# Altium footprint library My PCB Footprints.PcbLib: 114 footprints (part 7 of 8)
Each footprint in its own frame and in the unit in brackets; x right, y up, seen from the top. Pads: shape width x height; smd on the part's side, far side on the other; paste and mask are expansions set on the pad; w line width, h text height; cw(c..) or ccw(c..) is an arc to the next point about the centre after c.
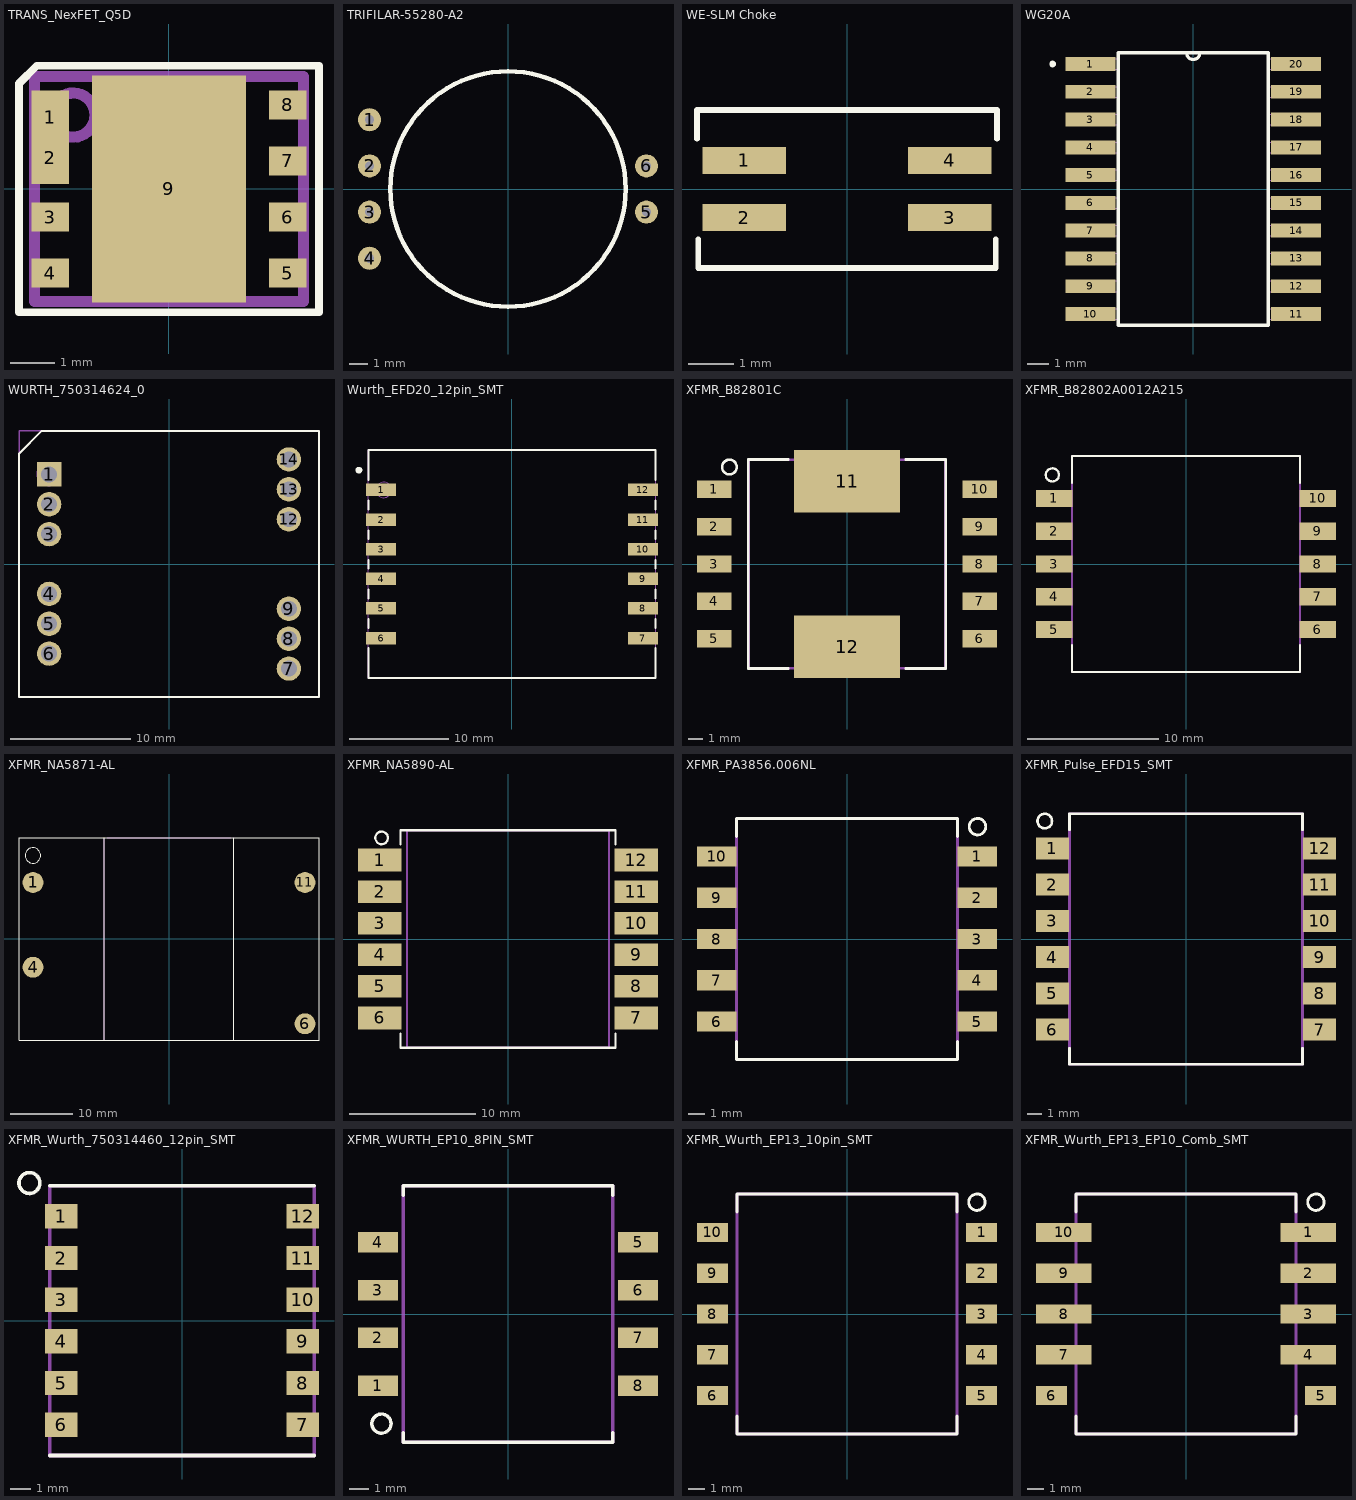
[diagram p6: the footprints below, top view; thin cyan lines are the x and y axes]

## TRANS_NexFET_Q5D [mm] "TI recommended land pattern (nominal) M0188-01"
height 1.5
pads (9):
  rect 0.85x1.2 smd paste-0.1 mask+0.051: 1(-2.695,1.63) 2(-2.695,0.71)
  rect 0.85x0.65 smd paste-0.1 mask+0.051: 3(-2.695,-0.635) 4(-2.695,-1.905) 5(2.695,-1.905) 6(2.695,-0.635) 7(2.695,0.635) 8(2.695,1.905)
  rect 3.48x5.15 smd paste-2.2 mask+0.051: 9(0,0)
Top Overlay:
  lines w0.178: -3.4,-2.795 -3.4,0 -3.4,2.39 -2.995,2.795 0,2.795 3.4,2.795 3.4,0 3.4,-2.795 0,-2.795 -3.4,-2.795
Top Paste:
  region: 0.15,0.15 0.15,2.125 1.45,2.125 1.45,0.15
  region: -1.45,0.15 -1.45,2.125 -0.15,2.125 -0.15,0.15
  region: 0.15,-2.125 0.15,-0.15 1.45,-0.15 1.45,-2.125
  region: -1.45,-2.125 -1.45,-0.15 -0.15,-0.15 -0.15,-2.125
Mechanical 5:
  text ".Designator" at -1.529,-0.508 h1.02
Mechanical 13:
  circle w0.254: c-2.175,1.675 r0.5
  lines w0.254: -3.05,-2.55 3.05,-2.55 3.05,2.55 -3.05,2.55 -3.05,-2.55
3D body: height 1.51, standoff 1, extent -2.684,1.166 -1.666,2.184
3D body: height 1.5, standoff 0, extent -3.05,-2.549 3.049,2.549

## TRIFILAR-55280-A2 [mil]
height 250
pads (6):
  round 50 hole 20: 1(-300,150) 2(-300,50) 3(-300,-50) 4(-300,-150) 5(300,-50) 6(300,50)
Top Overlay:
  circle w10: c0,0 r255

## WE-SLM Choke [mm] "WE-SLM SMD Common Mode Choke"
height 3.3
pads (4):
  rect 1.85x0.6 smd: 1(-2.275,0.635) 2(-2.275,-0.635) 3(2.275,-0.635) 4(2.275,0.635)
Top Overlay:
  lines w0.127: -3.327,1.118 -3.327,1.753 ; -3.302,-1.753 -3.302,-1.118 ; -3.302,-1.75 3.302,-1.75 ; -3.302,1.75 3.302,1.75 ; 3.302,-1.753 3.302,-1.118 ; 3.327,1.118 3.327,1.753
  text "." at -3.937,0.635 h1
  text "." at -3.937,-0.762 h1
Mechanical 5:
  text ".Designator" at -0.127,0 h1.02
3D body: height 3.3, standoff 0, extent -3.023,-1.651 3.023,1.651

## WG20A [mil]
pads (20):
  rect 90x25 smd: 1(-185,225) 2(-185,175) 3(-185,125) 4(-185,75) 5(-185,25) 6(-185,-25) 7(-185,-75) 8(-185,-125) 9(-185,-175) 10(-185,-225) 11(185,-225) 12(185,-175) 13(185,-125) 14(185,-75) 15(185,-25) 16(185,25) 17(185,75) 18(185,125) 19(185,175) 20(185,225)
Top Overlay:
  circle w6: c-253,225 r3
  lines w6: -12,245 ccw(c0,245) 12,245 ; -135,-245 135,-245 135,245 -135,245 -135,-245
Mechanical 1:
  circle w1: c-253,225 r3
  lines w1: -12,245 ccw(c0,245) 12,245 ; -210,-234.5 -135,-234.5 -135,-215.5 -210,-215.5 -210,-234.5 ; -210,-184.5 -135,-184.5 -135,-165.5 -210,-165.5 -210,-184.5 ; -210,-134.5 -210,-115.5 -135,-115.5 -135,-134.5 -210,-134.5 ; -210,-84.5 -210,-65.5 -135,-65.5 -135,-84.5 -210,-84.5 ; -210,-34.5 -210,-15.5 -135,-15.5 -135,-34.5 -210,-34.5 ; -210,15.5 -210,34.5 -135,34.5 -135,15.5 -210,15.5 ; -210,65.5 -210,84.5 -135,84.5 -135,65.5 -210,65.5 ; -210,115.5 -210,134.5 -135,134.5 -135,115.5 -210,115.5 ; -210,165.5 -210,184.5 -135,184.5 -135,165.5 -210,165.5 ; -210,215.5 -210,234.5 -135,234.5 -135,215.5 -210,215.5 ; -135,-245 135,-245 135,245 -135,245 -135,-245 ; 135,-234.5 210,-234.5 210,-215.5 135,-215.5 135,-234.5 ; 135,-184.5 210,-184.5 210,-165.5 135,-165.5 135,-184.5 ; 135,-134.5 135,-115.5 210,-115.5 210,-134.5 135,-134.5 ; 135,-84.5 135,-65.5 210,-65.5 210,-84.5 135,-84.5 ; 135,-34.5 135,-15.5 210,-15.5 210,-34.5 135,-34.5 ; 135,15.5 135,34.5 210,34.5 210,15.5 135,15.5 ; 135,65.5 135,84.5 210,84.5 210,65.5 135,65.5 ; 135,115.5 135,134.5 210,134.5 210,115.5 135,115.5 ; 135,165.5 135,184.5 210,184.5 210,165.5 135,165.5 ; 135,215.5 135,234.5 210,234.5 210,215.5 135,215.5

## WURTH_750314624_0 [mil] "WURTH EF20 through-hole, extended rail"
height 629.92
pads (12):
  rect 80x80 hole 52: 1(-393.5,294)
  round 80 hole 52: 2(-393.5,196) 3(-393.5,98) 4(-393.5,-98) 5(-393.5,-196) 6(-393.5,-294) 7(393.5,-343) 8(393.5,-245) 9(393.5,-147) 12(393.5,147) 13(393.5,245) 14(393.5,343)
Top Overlay:
  lines w6.69: -492.13,-437.01 -492.13,362.2 -417.32,437.01 492.13,437.01 492.13,-437.01 -492.13,-437.01
Mechanical 5:
  circle w40: c-395,295 r20
  lines w5: -492,-437 492,-437 492,437 -492,437 -492,-437
  text ".Designator" at -75,-15 h40
3D body: height 630, standoff 150, extent -335,-275 275,270
3D body: height 500, standoff 100, extent -50,-435 490,435
3D body: height 100, standoff 0, extent 338.7,-437.49 460,435
3D body: height 500, standoff 100, extent -490,-435 -50,435
3D body: height 501, standoff 400, extent -415.37,274.63 -374.63,315.37
3D body: height 100, standoff 0, extent -455,-435 -333.7,437.49

## Wurth_EFD20_12pin_SMT [mm] "WURTH EFD20 12pin SMT package"
height 11.43
pads (12):
  rect 3.05x1.27 smd: 1(-13.26,7.5) 2(-13.26,4.5) 3(-13.26,1.5) 4(-13.26,-1.5) 5(-13.26,-4.5) 6(-13.26,-7.5) 7(13.26,-7.5) 8(13.26,-4.5) 9(13.26,-1.5) 10(13.26,1.5) 11(13.26,4.5) 12(13.26,7.5)
Top Overlay:
  circle w0.5: c-15.5,9.5 r0.091
  lines w0.2: -14.54,-8.509 -14.54,-11.555 14.54,-11.555 14.54,-8.509 ; -14.54,-6.477 -14.54,-5.588 ; -14.54,-3.477 -14.54,-2.588 ; -14.54,-0.477 -14.54,0.412 ; -14.54,2.523 -14.54,3.412 ; -14.54,5.523 -14.54,6.412 ; -14.54,8.509 -14.54,11.555 14.54,11.555 14.54,8.509 ; 14.54,-6.477 14.54,-5.588 ; 14.54,-3.477 14.54,-2.588 ; 14.54,-0.477 14.54,0.412 ; 14.54,2.523 14.54,3.412 ; 14.54,5.523 14.54,6.412
Mechanical 5:
  circle w0.1: c-12.98,7.5 r0.776
  lines w0.1: -14.54,-11.555 -14.54,11.555 14.54,11.555 14.54,-11.555 -14.54,-11.555
  text ".Designator" at 0.508,-1.524 h1.02
3D body: height 11.43, standoff 11.43, extent -13.479,7.004 -12.481,8
3D body: height 11.43, standoff 0, extent -14.54,-11.555 14.54,11.555

## XFMR_B82801C [mm] "Recommended land pattern for EPCOS B82801C transformer"
height 10
pads (12):
  rect 2.335x1.19 smd: 1(-9.042,5.08) 2(-9.042,2.54) 3(-9.042,0) 4(-9.042,-2.54) 5(-9.042,-5.08) 6(9.042,-5.08) 7(9.042,-2.54) 8(9.042,0) 9(9.042,2.54) 10(9.042,5.08)
  rect 7.24x4.25 smd: 11(0,5.62) 12(0,-5.62)
Top Overlay:
  circle w0.178: c-8,6.6 r0.5
  lines w0.178: -4,-7.11 -6.73,-7.11 -6.73,7.11 -4,7.11 ; 4,-7.11 6.73,-7.11 6.73,7.11 4,7.11
Mechanical 5:
  text ".designator" at -1.219,-0.635 h1.52
Mechanical 13:
  lines w0.178: -6.7,-7.1 -6.7,7.1 6.7,7.1 6.7,-7.1 -6.7,-7.1
3D body: height 10, standoff 8.89, extent -5.761,4.739 -4.239,6.261
3D body: height 10, standoff 0, extent -6.7,-7.1 6.7,7.1

## XFMR_B82802A0012A215 [mm] "Recommended land pattern for EPCOS EFD15 B82802A0012A215/315 transformer"
height 8.65
pads (10):
  rect 2.8x1.3 smd: 1(-10.05,5) 2(-10.05,2.5) 3(-10.05,0) 4(-10.05,-2.5) 5(-10.05,-5) 6(10.05,-5) 7(10.05,-2.5) 8(10.05,0) 9(10.05,2.5) 10(10.05,5)
Top Overlay:
  circle w0.178: c-10.2,6.8 r0.5
  lines w0.178: -8.7,-6.2 -8.7,-8.25 0.9,-8.25 8.7,-8.25 ; -8.7,6.2 -8.7,8.2 ; -8.7,8.25 -0.9,8.25 8.7,8.25 ; 8.7,-8.2 8.7,-6.2 ; 8.7,6.2 8.7,8.2
Mechanical 5:
  text ".designator" at -1.219,-0.635 h1.52
Mechanical 13:
  lines w0.178: -8.7,-8.25 8.7,-8.25 8.7,8.25 -8.7,8.25 ; -8.7,-8.2 -8.7,8.2
3D body: height 8.66, standoff 8.65, extent -7.561,5.639 -6.039,7.161
3D body: height 8.65, standoff 0, extent -8.6,-8 8.5,8.1

## XFMR_NA5871-AL [mm] "Recommended land pattern for Coilcraft NA5871-AL transformer"
height 16.51
pads (4):
  round 3.38 smd: 1(-21.98,9.14) 4(-21.98,-4.57) 6(21.98,-13.71) 11(21.98,9.14)
Top Overlay:
  circle w0.178: c-22,13.5 r1.25
  lines w0.178: -24.25,-16.36 -24.25,0 -24.25,16.35 0,16.35 24.25,16.35 24.25,0 24.25,-16.35 0,-16.35 -24.25,-16.35 ; -10.5,-16.35 -10.5,16.35 ; 10.5,-16.35 10.5,16.35
Mechanical 5:
  text ".designator" at -1.219,-0.635 h1.52
Mechanical 13:
  lines w0.178: -10.5,-16.35 -10.5,16.35 ; -10,-16.35 10,-16.35 ; -10,16.35 10,16.35 ; 10.5,-16.35 10.5,16.35
3D body: height 13.5, standoff 13.5, extent -8.261,11.739 -6.739,13.261
3D body: height 16.51, standoff 0, extent -10.5,-16.35 10.5,16.35

## XFMR_NA5890-AL [mm] "Recommended land pattern for Coilcraft NA5890-AL transformer"
height 8.89
pads (12):
  rect 3.43x1.79 smd: 1(-10.155,6.25) 2(-10.155,3.75) 3(-10.155,1.25) 4(-10.155,-1.25) 5(-10.155,-3.75) 6(-10.155,-6.25) 7(10.155,-6.25) 8(10.155,-3.75) 9(10.155,-1.25) 10(10.155,1.25) 11(10.155,3.75) 12(10.155,6.25)
Top Overlay:
  circle w0.178: c-10,8 r0.5
  lines w0.178: -8.5,-7.5 -8.5,-8.6 0,-8.6 8.5,-8.6 8.5,-7.5 ; -8.5,7.5 -8.5,8.6 0,8.6 8.5,8.6 8.5,7.5
Mechanical 5:
  text ".designator" at -1.219,-0.635 h1.52
Mechanical 13:
  lines w0.178: -8,-8.6 8,-8.6 8,8.6 -8,8.6 -8,-8.6
3D body: height 8.89, standoff 0, extent -8,-8.6 8,8.6
3D body: height 8.89, standoff 8.89, extent -6.761,5.739 -5.239,7.261

## XFMR_PA3856.006NL [mm] "Recommended land pattern for Pulse Engineering PA3856.006NL transformer"
height 14
pads (10):
  rect 2.4x1.22 smd: 1(7.88,5) 2(7.88,2.5) 3(7.88,0) 4(7.88,-2.5) 5(7.88,-5) 6(-7.88,-5) 7(-7.88,-2.5) 8(-7.88,0) 9(-7.88,2.5) 10(-7.88,5)
Top Overlay:
  circle w0.178: c7.9,6.8 r0.5
  lines w0.178: -6.7,-6.2 -6.7,-7.3 0,-7.3 6.7,-7.3 6.7,-6.2 ; -6.7,6.2 -6.7,7.3 0,7.3 6.7,7.3 6.7,6.2
Mechanical 5:
  text ".designator" at -1.219,-0.635 h1.52
Mechanical 13:
  lines w0.178: -6.7,-7.3 6.7,-7.3 6.7,7.3 -6.7,7.3 -6.7,-7.3
3D body: height 14, standoff 0, extent -6.7,-7.3 6.7,7.3
3D body: height 14.01, standoff 14, extent 4.239,4.239 5.761,5.761

## XFMR_Pulse_EFD15_SMT [mm] "Recommended land pattern for Pulse EFD 15 Platforms - SMT"
height 8.38
pads (12):
  rect 2.26x1.52 smd: 1(-9.17,6.225) 2(-9.17,3.735) 3(-9.17,1.245) 4(-9.17,-1.245) 5(-9.17,-3.735) 6(-9.17,-6.225) 7(9.17,-6.225) 8(9.17,-3.735) 9(9.17,-1.245) 10(9.17,1.245) 11(9.17,3.735) 12(9.17,6.225)
Top Overlay:
  circle w0.178: c-9.7,8.1 r0.5
  lines w0.178: -8,-7.5 -8,-8.6 0,-8.6 8,-8.6 8,-7.5 ; -8,7.5 -8,8.6 0,8.6 8,8.6 8,7.5
Mechanical 5:
  text ".designator" at -1,-0.5 h1.52
Mechanical 13:
  lines w0.178: -8,-8.6 8,-8.6 8,8.6 -8,8.6 -8,-8.6
3D body: height 8.38, standoff 0, extent -8,-8.6 8,8.6
3D body: height 8.38, standoff 8.38, extent -6.561,5.439 -5.039,6.961

## XFMR_Wurth_750314460_12pin_SMT [mm] "Recommended land pattern for Wurth - SMT"
height 5.98
pads (12):
  rect 1.57x1.17 smd: 1(-5.79,5) 2(-5.79,3) 3(-5.79,1) 4(-5.79,-1) 5(-5.79,-3) 6(-5.79,-5) 7(5.79,-5) 8(5.79,-3) 9(5.79,-1) 10(5.79,1) 11(5.79,3) 12(5.79,5)
Top Overlay:
  circle w0.178: c-7.325,6.6 r0.5
  lines w0.178: -6.35,-6.475 0,-6.475 6.35,-6.475 ; -6.35,6.475 0,6.475 6.35,6.475
Mechanical 5:
  text ".designator" at -1,-0.5 h1.52
Mechanical 13:
  lines w0.178: -6.35,-6.475 -6.35,6.475 6.35,6.475 6.35,-6.475 -6.35,-6.475
3D body: height 6.35, standoff 6.35, extent -3.861,4.239 -2.339,5.761
3D body: height 6.35, standoff 0, extent -6.35,-6.475 6.35,6.475

## XFMR_WURTH_EP10_8PIN_SMT [mm] "Recommended land pattern for Wurth EP10 8 pin transformer"
height 11.43
pads (8):
  rect 2.08x1.07 smd: 1(-6.78,-3.735) 2(-6.78,-1.245) 3(-6.78,1.245) 4(-6.78,3.735) 5(6.78,3.735) 6(6.78,1.245) 7(6.78,-1.245) 8(6.78,-3.735)
Top Overlay:
  circle w0.178: c-6.596,-5.715 r0.5
  lines w0.178: -5.461,-6.2 -5.461,-6.68 -0.67,-6.68 5.461,-6.68 5.461,-6.2 ; -5.461,6.2 -5.461,6.68 0.67,6.68 5.461,6.68 5.461,6.2
Mechanical 5:
  text ".designator" at -1.219,-0.635 h1.52
Mechanical 13:
  lines w0.178: -5.461,-6.68 5.461,-6.68 5.461,6.68 -5.461,6.68 -5.461,-6.68
3D body: height 11.43, standoff 0, extent -5.461,-6.604 5.461,6.604
3D body: height 11.44, standoff 11.43, extent -4.571,-5.841 -3.049,-4.319

## XFMR_Wurth_EP13_10pin_SMT [mm] "Recommended land pattern for Wurth EP13 package (10pin) transformer"
height 14
pads (10):
  rect 1.88x1.17 smd: 1(8.18,4.96) 2(8.18,2.48) 3(8.18,0) 4(8.18,-2.48) 5(8.18,-4.96) 6(-8.18,-4.96) 7(-8.18,-2.48) 8(-8.18,0) 9(-8.18,2.48) 10(-8.18,4.96)
Top Overlay:
  circle w0.178: c7.9,6.8 r0.5
  lines w0.178: -6.7,-6.2 -6.7,-7.3 0,-7.3 6.7,-7.3 6.7,-6.2 ; -6.7,6.2 -6.7,7.3 0,7.3 6.7,7.3 6.7,6.2
Mechanical 5:
  text ".designator" at -1.219,-0.635 h1.52
Mechanical 13:
  lines w0.178: -6.7,-7.3 -6.7,7.3 6.7,7.3 6.7,-7.3 -6.7,-7.3
3D body: height 12.71, standoff 12.7, extent 4.239,4.239 5.761,5.761
3D body: height 12.7, standoff 0, extent -6.7,-7.3 6.7,7.3

## XFMR_Wurth_EP13_EP10_Comb_SMT [mm] "Recommended land pattern for Wurth EP13 package (10pin) transformer"
height 14
pads (10):
  rect 3.38x1.17 smd: 1(7.43,4.96) 2(7.43,2.48) 3(7.43,0) 4(7.43,-2.48) 7(-7.43,-2.48) 8(-7.43,0) 9(-7.43,2.48) 10(-7.43,4.96)
  rect 1.88x1.17 smd: 5(8.18,-4.96) 6(-8.18,-4.96)
Top Overlay:
  circle w0.178: c7.9,6.8 r0.5
  lines w0.178: -6.7,-6.2 -6.7,-7.3 0,-7.3 6.7,-7.3 6.7,-6.2 ; -6.7,6.2 -6.7,7.3 0,7.3 6.7,7.3 6.7,6.2
Mechanical 5:
  text ".designator" at -1.219,-0.635 h1.52
Mechanical 13:
  lines w0.178: -6.7,-7.3 6.7,-7.3 6.7,7.3 -6.7,7.3 -6.7,-7.3
3D body: height 12.7, standoff 0, extent -6.7,-7.3 6.7,7.3
3D body: height 12.71, standoff 12.7, extent 4.239,4.239 5.761,5.761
